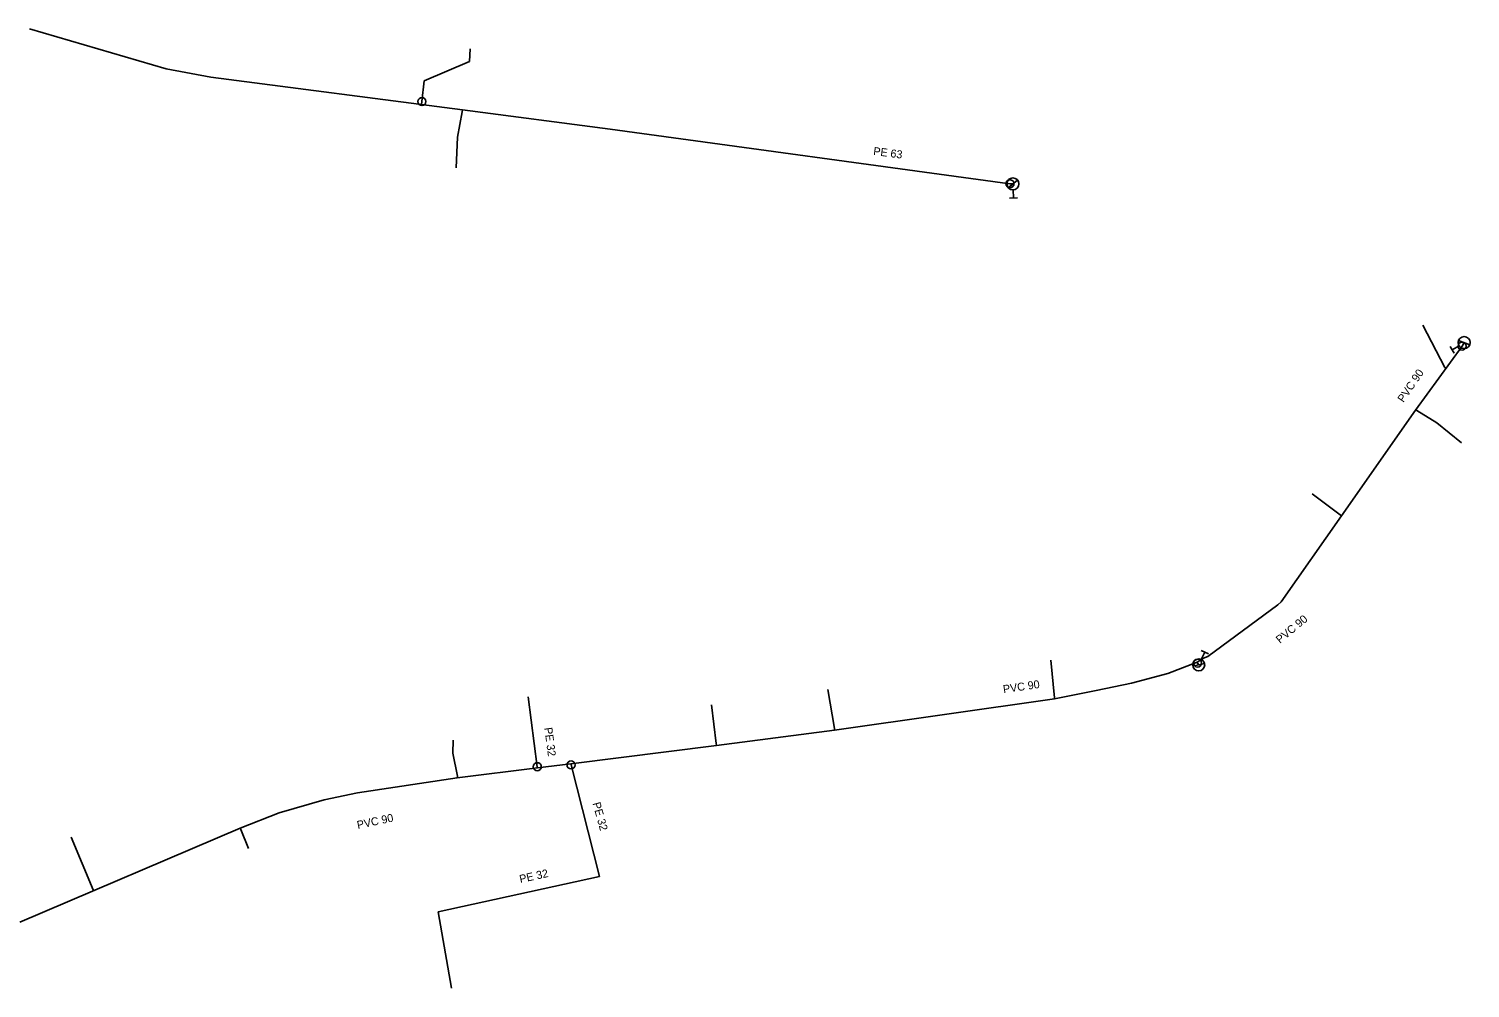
# Model space of a CAD drawing. Extents: x -643485 to -643037, y -1068047 to -1067198.
# Drawn here: x -643217.2 to -643037.1, y -1067318.3 to -1067198.5 of the extents above; entities that cross this region are included whole.
import ezdxf

# ---------------------------------------------------------------- set-up
doc = ezdxf.new("R2010")
doc.units = 0
doc.layers.add('Level 0', color=7, linetype='Continuous')

msp = doc.modelspace()

# ---------------------------------------------------------------- linework, layer by layer
at = {"layer": 'Level 0'}
for p, q in [((-643217.1, -1067198.46), (-643200.02, -1067203.44)), ((-643162.04, -1067200.96), (-643162.14, -1067202.54)), ((-643200.02, -1067203.44), (-643194.45, -1067204.48)), ((-643162.14, -1067202.54), (-643167.8, -1067204.95)), ((-643194.45, -1067204.48), (-643163.02, -1067208.56)), ((-643167.8, -1067204.95), (-643168.09, -1067207.54)), ((-643168.09, -1067207.54), (-643168.13, -1067207.9)), ((-643163.07, -1067208.81), (-643163.66, -1067211.98)), ((-643163.02, -1067208.56), (-643163.07, -1067208.81)), ((-643163.02, -1067208.56), (-643144.59, -1067210.98)), ((-643144.59, -1067210.98), (-643094.62, -1067217.81)), ((-643163.66, -1067211.98), (-643163.81, -1067215.81)), ((-643093.69, -1067217.35), (-643094.84, -1067218.31)), ((-643094.62, -1067217.81), (-643094.26, -1067217.83)), ((-643093.7, -1067219.56), (-643094.7, -1067219.6)), ((-643094.23, -1067218.58), (-643094.2, -1067219.58)), ((-643040.3, -1067240.78), (-643043.06, -1067235.49)), ((-643038.52, -1067238.05), (-643039.37, -1067238.57)), ((-643037.18, -1067237.92), (-643038.58, -1067237.4)), ((-643038.14, -1067238.1), (-643037.88, -1067237.66)), ((-643043.95, -1067246.1), (-643038.14, -1067238.1)), ((-643039.11, -1067239), (-643039.63, -1067238.15)), ((-643040.14, -1067240.86), (-643040.3, -1067240.78)), ((-643053.19, -1067259.31), (-643043.95, -1067246.1)), ((-643043.95, -1067246.1), (-643043.81, -1067246.16)), ((-643043.81, -1067246.16), (-643041.31, -1067247.69)), ((-643041.31, -1067247.69), (-643038.21, -1067250.18)), ((-643053.37, -1067259.18), (-643056.85, -1067256.55)), ((-643060.76, -1067270.06), (-643053.19, -1067259.31)), ((-643053.19, -1067259.31), (-643053.37, -1067259.18)), ((-643069.91, -1067276.86), (-643061.17, -1067270.4)), ((-643061.17, -1067270.4), (-643060.76, -1067270.06)), ((-643089.07, -1067282.02), (-643089.53, -1067277.32)), ((-643074.91, -1067278.98), (-643071.25, -1067277.57)), ((-643071.25, -1067277.57), (-643070.45, -1067277.08)), ((-643071.25, -1067277.57), (-643071.19, -1067277.69)), ((-643070.75, -1067276.12), (-643069.84, -1067276.55)), ((-643070.72, -1067277.24), (-643070.29, -1067276.34)), ((-643070.45, -1067277.08), (-643069.91, -1067276.86)), ((-643079.42, -1067280.22), (-643074.91, -1067278.98)), ((-643071.77, -1067278.09), (-643070.31, -1067277.75)), ((-643071.19, -1067277.69), (-643071.04, -1067277.92)), ((-643116.53, -1067285.89), (-643117.37, -1067281.01)), ((-643089.04, -1067282.18), (-643083.85, -1067281.14)), ((-643083.85, -1067281.14), (-643079.42, -1067280.22)), ((-643153.67, -1067290.64), (-643154.82, -1067281.9)), ((-643131.32, -1067287.76), (-643131.89, -1067282.92)), ((-643116.53, -1067286.07), (-643089.04, -1067282.18)), ((-643089.04, -1067282.18), (-643089.07, -1067282.02)), ((-643131.29, -1067287.99), (-643116.53, -1067286.07)), ((-643116.53, -1067286.07), (-643116.53, -1067285.89)), ((-643164.24, -1067288.95), (-643164.17, -1067287.34)), ((-643149.5, -1067290.27), (-643131.29, -1067287.99)), ((-643131.29, -1067287.99), (-643131.32, -1067287.76)), ((-643163.66, -1067291.83), (-643164.24, -1067288.95)), ((-643153.65, -1067290.79), (-643149.5, -1067290.27)), ((-643149.5, -1067290.27), (-643149.46, -1067290.42)), ((-643176.14, -1067293.92), (-643163.67, -1067292.05)), ((-643163.67, -1067292.05), (-643153.65, -1067290.79)), ((-643163.67, -1067292.05), (-643163.66, -1067291.83)), ((-643153.65, -1067290.79), (-643153.67, -1067290.64)), ((-643149.46, -1067290.42), (-643145.89, -1067304.37)), ((-643185.9, -1067296.39), (-643180.29, -1067294.8)), ((-643180.29, -1067294.8), (-643176.14, -1067293.92)), ((-643190.8, -1067298.31), (-643185.9, -1067296.39)), ((-643218.3, -1067310.06), (-643190.8, -1067298.31)), ((-643190.8, -1067298.31), (-643190.72, -1067298.47)), ((-643190.72, -1067298.47), (-643189.74, -1067300.88)), ((-643209.17, -1067306.01), (-643211.91, -1067299.43)), ((-643145.89, -1067304.37), (-643166.07, -1067308.78)), ((-643209.12, -1067306.14), (-643209.17, -1067306.01)), ((-643166.07, -1067308.78), (-643164.4, -1067318.31))]:
    msp.add_line(p, q, dxfattribs=at)
for centre, radius in [((-643168.09, -1067207.54), 0.5), ((-643094.62, -1067217.81), 0.5), ((-643094.26, -1067217.83), 0.75), ((-643038.14, -1067238.1), 0.5), ((-643037.88, -1067237.66), 0.75), ((-643071.04, -1067277.92), 0.75), ((-643071.19, -1067277.69), 0.5), ((-643153.67, -1067290.64), 0.5), ((-643149.46, -1067290.42), 0.5)]:
    msp.add_circle(centre, radius, dxfattribs=at)

# ---------------------------------------------------------------- texts
for s, rotation, p in [('PE 63', 352.604, (-643111.74, -1067214.21)), ('PVC 90', 55.732, (-643045.46, -1067245.22)), ('PVC 90', 39.668, (-643060.89, -1067275.3)), ('PVC 90', 8.236, (-643095.42, -1067281.46)), ('PE 32', 277.496, (-643152.8, -1067285.79)), ('PE 32', 285.531, (-643146.78, -1067295.22)), ('PVC 90', 11.972, (-643176.09, -1067298.43)), ('PE 32', 12.327, (-643155.79, -1067305.18))]:
    msp.add_text(s, height=1, rotation=rotation, dxfattribs=at).set_placement(p)

doc.saveas('drawing.dxf')
